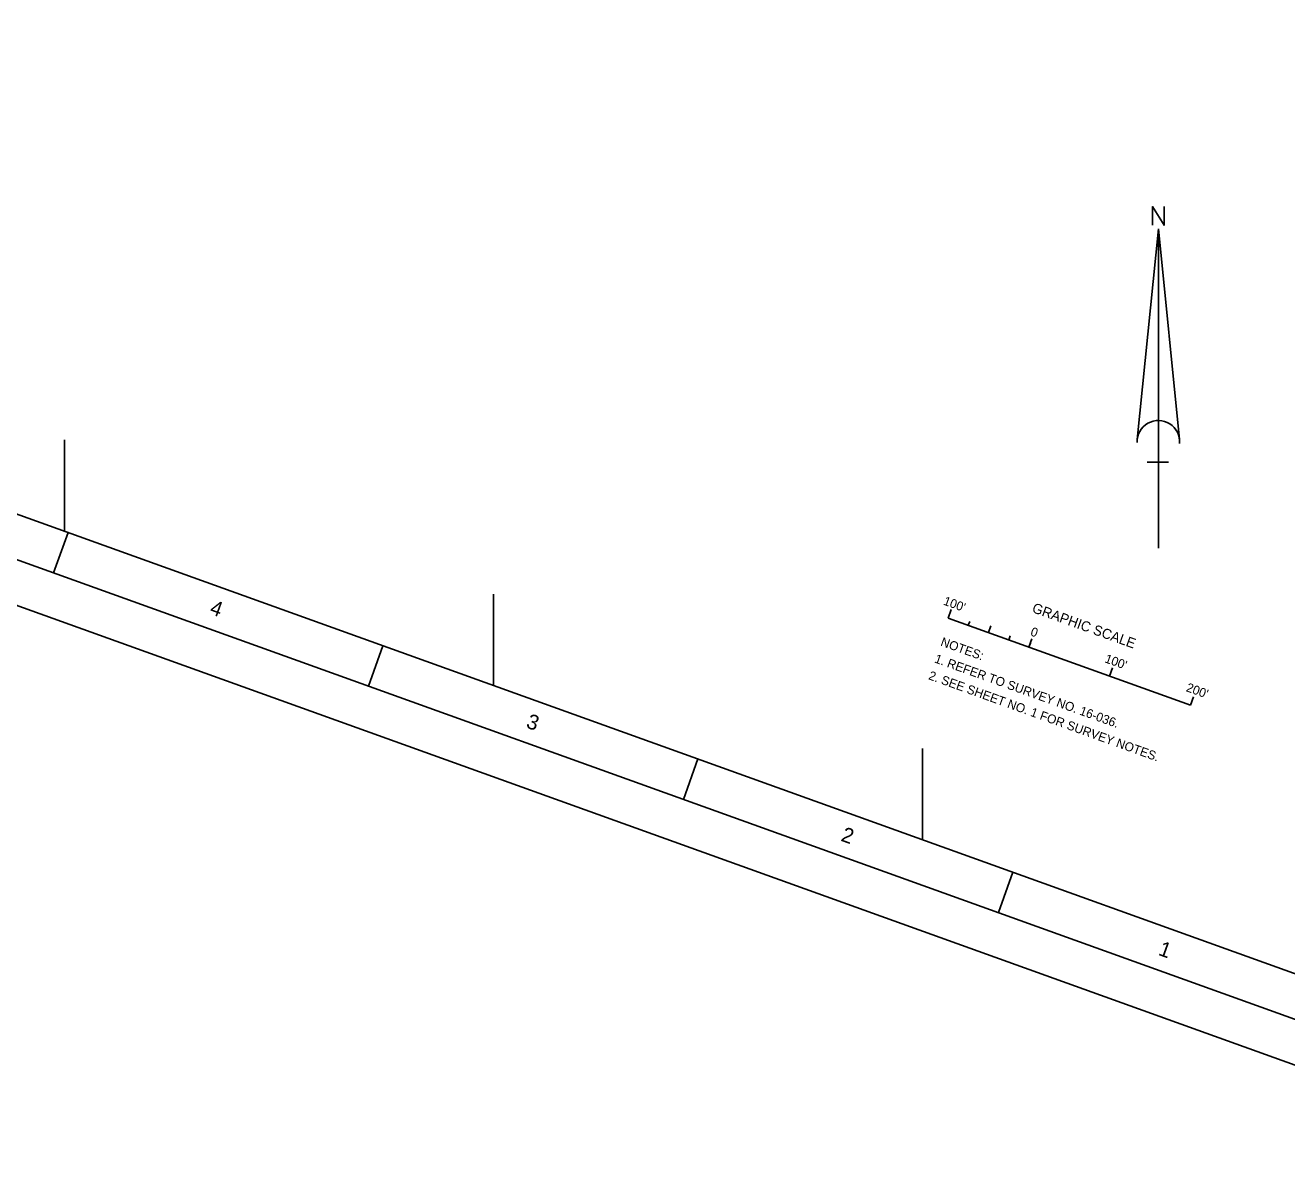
# Model space of a CAD drawing. Extents: x 609104 to 614395, y 782051 to 786739.
# Drawn here: x 611454 to 612925, y 782051 to 783373 of the extents above; entities that cross this region are included whole.
import ezdxf

# ---------------------------------------------------------------- set-up
doc = ezdxf.new("R2010")
doc.units = 0
for name, color, linetype in [('G-ANNO-NPLT', 7, 'Continuous'), ('G-ANNO-TTLB', 7, 'Continuous'), ('V-ANNO-NOTE', 7, 'Continuous'), ('V-ANNO-SYMB', 7, 'Continuous'), ('V-TOPO-COOR-STAT', 7, 'Continuous')]:
    doc.layers.add(name, color=color, linetype=linetype)

msp = doc.modelspace()

# ---------------------------------------------------------------- linework, layer by layer
at = {"layer": 'G-ANNO-NPLT'}
msp.add_lwpolyline([(610254.1, 786738.7), (614394.6, 785250.1), (613244.3, 782050.6), (609103.8, 783539.2)], close=True, dxfattribs=at)
at = {"layer": 'G-ANNO-TTLB'}
for p, q in [((611487.4, 782735.4), (611504.3, 782782.5)), ((611854.4, 782603.5), (611871.3, 782650.5)), ((612221.4, 782471.5), (612238.3, 782518.6)), ((612588.4, 782339.6), (612605.3, 782386.6))]:
    msp.add_line(p, q, dxfattribs=at)
for points in [[(609167.8, 783569.4), (613214.2, 782114.6), (614330.7, 785220), (610284.3, 786674.7)], [(614266.7, 785189.8), (610385, 786585.4), (609302.3, 783574.1), (613184.1, 782178.5)]]:
    msp.add_lwpolyline(points, close=True, dxfattribs=at)
at = {"layer": 'V-ANNO-NOTE'}
for p, q in [((612529.9, 782682.7), (612533.4, 782692.6)), ((612529.9, 782682.7), (612812.2, 782581.2)), ((612553.4, 782674.3), (612555, 782678.8)), ((612576.9, 782665.8), (612579.8, 782673.8)), ((612600.5, 782657.4), (612602.1, 782661.9)), ((612624, 782648.9), (612627.5, 782658.7)), ((612624, 782648.9), (612627.5, 782658.7)), ((612624, 782648.9), (612625.7, 782653.6)), ((612718.1, 782615.1), (612721.6, 782624.9)), ((612812.2, 782581.2), (612815.7, 782591.1))]:
    msp.add_line(p, q, dxfattribs=at)
at = {"layer": 'V-ANNO-SYMB'}
for p, q in [((612750.2, 782890.6), (612774.9, 783136.3)), ((612774.9, 782764), (612774.9, 783136.3)), ((612799.6, 782890.6), (612774.9, 783136.3)), ((612786.7, 782864.5), (612761.8, 782864.5))]:
    msp.add_line(p, q, dxfattribs=at)
msp.add_lwpolyline([(612768, 783140.3), (612768, 783162), (612781.5, 783140.3), (612781.5, 783162)], dxfattribs=at)
msp.add_arc((612774.9, 782888.1), 24.8, 355.2984, 182.0673, dxfattribs=at)
at = {"layer": 'V-TOPO-COOR-STAT'}
for p, q in [((611500, 782784), (611500, 782890.3)), ((612000, 782604.3), (612000, 782710.5)), ((612500, 782424.5), (612500, 782530.8))]:
    msp.add_line(p, q, dxfattribs=at)

# ---------------------------------------------------------------- texts
at = {"layer": 'G-ANNO-TTLB'}
for s, p in [('4', (611668.4, 782688)), ('3', (612037.1, 782555.5)), ('2', (612403.9, 782423.6)), ('1', (612773.9, 782290.6))]:
    msp.add_text(s, height=17.5, rotation=340.2251, dxfattribs=at).set_placement(p)
at = {"layer": 'V-ANNO-NOTE'}
for s, height, p in [("100'", 10.42, (612523.5, 782698.6)), ('GRAPHIC SCALE', 11.666, (612626.8, 782689.9)), ('0', 10.4, (612625, 782662.8)), ('NOTES:', 10.42, (612520.3, 782650.9)), ('1. REFER TO SURVEY NO. 16-036.', 10.416, (612513.2, 782631.3)), ("100'", 10.42, (612711.6, 782631.4)), ('2. SEE SHEET NO. 1 FOR SURVEY NOTES.', 10.416, (612506.2, 782611.7)), ("200'", 10.42, (612806.4, 782597.8))]:
    msp.add_text(s, height=height, rotation=340.2251, dxfattribs=at).set_placement(p)

doc.saveas('drawing.dxf')
